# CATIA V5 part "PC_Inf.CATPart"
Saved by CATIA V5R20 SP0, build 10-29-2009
Part number: PC_Inf
Bounding box of the stored display mesh (mm): x -248 to 248, y -198 to 198, z 0 to 116
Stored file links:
  C:\Users\Escafandra\Desktop\2º\0_PLÁSTICOS\Eres La Mejor\PC_Inf.CATPart
  C:\Users\Escafandra\Desktop\2º\0_PLÁSTICOS\Eres La Mejor\Impronta_Fija.CATPart
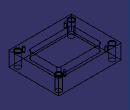
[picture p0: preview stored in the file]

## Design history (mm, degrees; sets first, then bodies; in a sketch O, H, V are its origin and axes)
AxisSystem1: origin (0, 0, 0), X (1, 0, 0), Y (0, 1, 0), Z (0, 0, 1)
Body1 (main body)
  Sketch1 on xy-plane, origin (0, 0, 0), H (1, 0, 0), V (0, 1, 0)
    line L1 (248, 198) -> (248, -198)
    line L2 (248, -198) -> (-248, -198)
    line L3 (-248, -198) -> (-248, 198)
    line L4 (-248, 198) -> (248, 198)
    length L4 = 496
    length L1 = 396
    vertical: L1 V, L3 V
    horizontal: L2 H, L4 H
    equidistance: L1 L3 O, L2 L4 O
  Pad1: profile Sketch1, direction (0, 0, 1), length 116
  Body2
    Solid1: solid without history
    Translate1: Direction edge [ZX plane of AxisSystem1 | YZ plane of AxisSystem1], Length -186.034, ToTransfor Solid1
  Remove1: tool Body2
  Sketch2 on end face of Pad1, origin (0, 0, 116), H (1, 0, 0), V (0, 1, 0)
    line L1 (172.5, 102.5) -> (172.5, -102.5)
    line L2 (152.5, -122.5) -> (-152.5, -122.5)
    line L3 (-172.5, -102.5) -> (-172.5, 102.5)
    line L4 (-152.5, 122.5) -> (152.5, 122.5)
    point P1 (172.5, 122.5)
    point P2 (172.5, -122.5)
    point P3 (-172.5, 122.5)
    arc A1 centre (152.5, 102.5) radius 20 from (152.5, 122.5) to (172.5, 102.5) cw
    arc A2 centre (-152.5, 102.5) radius 20 from (-172.5, 102.5) to (-152.5, 122.5) cw
    arc A3 centre (-152.5, -102.5) radius 20 from (-152.5, -122.5) to (-172.5, -102.5) cw
    arc A4 centre (152.5, -102.5) radius 20 from (152.5, -122.5) to (172.5, -102.5) ccw
    distance P3 P1 = 345
    distance P1 P2 = 245
    radius A1 = 20
    radius A2 = 20
    radius A3 = 20
    radius A4 = 20
    vertical: L1 V, L3 V
    horizontal: L2 H, L4 H
    equidistance: L1 L3 O, L2 L4 O
    coincidence: L4 P1, L1 P1, L3 P3, L4 P3, L2 P2, L1 P2
    tangency: A1 L4, A1 L1, A2 L3, A2 L4, A3 L2, A3 L3, A4 L2, A4 L1
  Pocket1: profile Sketch2, direction (0, 0, -1), length 55.8
  Sketch3 on end face of Pad1, origin (-212, -162, 116), H (1, 0, 0), V (0, 1, 0)
    point P1 (0, 0)
    reference projected point E1 (0, 0) from Sketch11.P3
    coincidence: E1 P1
  Hole1: placed by Sketch3, at (-212, -162, 116) direction (0, 0, -1), diameter 42, through (limit type 3), counterbore diameter 48, counterbore depth 6.3
  Sketch4 on end face of Pad1, origin (-212, -162, 116), H (1, 0, 0), V (0, 1, 0)
    point P1 (424, 0)
    reference projected point E1 (424, 0) from Sketch11.P2
    coincidence: P1 E1
  Hole2: placed by Sketch4, at (212, -162, 116) direction (0, 0, -1), diameter 42, through (limit type 3), counterbore diameter 48, counterbore depth 6.3
  Sketch5 on end face of Pad1, origin (-212, -162, 116), H (1, 0, 0), V (0, 1, 0)
    point P1 (424, 324)
    reference projected point E1 (424, 324) from Sketch11.P1
    coincidence: P1 E1
  Hole3: placed by Sketch5, at (212, 162, 116) direction (0, 0, -1), diameter 42, through (limit type 3), counterbore diameter 48, counterbore depth 6.3
  Sketch6 on end face of Pad1, origin (-212, -162, 116), H (1, 0, 0), V (0, 1, 0)
    point P1 (0, 324)
    reference projected point E1 (0, 324) from Sketch11.P4
    coincidence: P1 E1
  Hole4: placed by Sketch6, at (-212, 162, 116) direction (0, 0, -1), diameter 42, through (limit type 3), counterbore diameter 48, counterbore depth 6.3
  Sketch7 on end face of Pad1, origin (-165, -162, 116), H (1, 0, 0), V (0, 1, 0)
    point P1 (0, 0)
    reference projected point E1 (0, 0) from Sketch11.P7
    coincidence: E1 P1
  Hole5: placed by Sketch7, at (-165, -162, 116) direction (0, 0, -1), diameter 16, depth 36, V-bottom angle 120
  Sketch8 on end face of Pad1, origin (-165, 162, 116), H (1, 0, 0), V (0, 1, 0)
    point P1 (0, 0)
    reference projected point E1 (0, 0) from Sketch11.P5
    coincidence: E1 P1
  Hole6: placed by Sketch8, at (-165, 162, 116) direction (0, 0, -1), diameter 16, depth 36, V-bottom angle 120
  Sketch9 on end face of Pad1, origin (165, 162, 116), H (1, 0, 0), V (0, 1, 0)
    point P1 (0, 0)
    reference projected point E1 (0, 0) from Sketch11.P6
    coincidence: E1 P1
  Hole7: placed by Sketch9, at (165, 162, 116) direction (0, 0, -1), diameter 16, depth 36, V-bottom angle 120
  Sketch10 on end face of Pad1, origin (165, -162, 116), H (1, 0, 0), V (0, 1, 0)
    point P1 (0, 0)
    reference projected point E1 (0, 0) from Sketch11.P8
    coincidence: E1 P1
  Hole8: placed by Sketch10, at (165, -162, 116) direction (0, 0, -1), diameter 16, depth 36, V-bottom angle 120
  Sketch11 on end face of Pad1, origin (0, 0, 116), H (1, 0, 0), V (0, 1, 0)
    construction line L1 (212, 162) -> (212, -162)
    construction line L2 (212, -162) -> (-212, -162)
    construction line L3 (-212, -162) -> (-212, 162)
    construction line L4 (-212, 162) -> (212, 162)
    point P1 (212, 162)
    point P2 (212, -162)
    point P3 (-212, -162)
    point P4 (-212, 162)
    point P5 (-165, 162)
    point P6 (165, 162)
    point P7 (-165, -162)
    point P8 (165, -162)
    length L4 = 424
    length L1 = 324
    distance P5 V = 165
    vertical: L1 V, L3 V
    horizontal: L2 H, L4 H
    equidistance: L1 L3 O, L2 L4 O
    coincidence: P5 L4
    symmetry: P5 P6 V, P5 P7 H, P6 P8 H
